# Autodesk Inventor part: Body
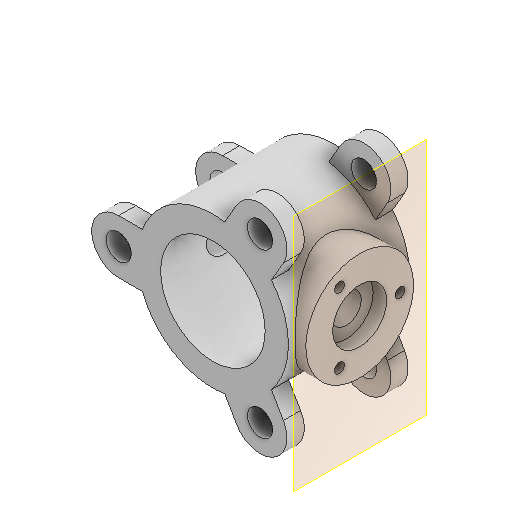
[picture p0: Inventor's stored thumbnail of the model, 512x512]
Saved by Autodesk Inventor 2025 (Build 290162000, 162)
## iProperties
Created: 2019-03
Part Number: Body
Material: Generic
Document SubType Name: Modeling
Designer: LENOVO-CADCIM
Density: 1 g/cm^3
Appearance: Default
Author: LENOVO-CADCIM
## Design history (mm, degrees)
sketch "Sketch1"
  geometry: C1 r 140 at (0, 0); C2 r 97 at (0, 0); 1 further point
  constraints: 2 centre point, 2 coincident
  dimensions: "d0" = 194 diameter of C2; "d1" = 280 diameter of C1
extrude "Extrusion1" new body sketch "Sketch1" stored distance "d2" = 225; taper "d3" = 0 deg
sketch "Sketch2"
  geometry: L1 (0, 0)-(-428, 0); L2 (-130.767, 50)-(-175, 50); L3 (-130.767, -50)-(-175, -50); C1 r 23.5 at (-175, 0); A1 r 175 centre (0, 0) between (-175, 0) and (-175, 0); A2 r 140 centre (0, 0) between (-130.767, 50) and (-130.767, -50) reference; A3 r 50 centre (-175, 0) between (-175, 50) and (-175, -50); 1 further point
  constraints: 6 end point, 6 point on circle, 3 centre point, 3 horizontal, 2 tangent, 1 coincident, 1 point on line, 1 other
  dimensions: "d4" = 350 diameter of A1; "d5" = 50 radius of A3; "d6" = 47 diameter of C1
extrude "Extrusion2" join sketch "Sketch2" distance "d7" = 32; taper "d8" = 0 deg
pattern_circular "Circular Pattern1" dims angle "d10" = 360 deg
mirror "Mirror1"
workplane "Work Plane1"
sketch "Sketch3"
  geometry: C1 r 100 at (0, 0); 1 further point
  constraints: 1 centre point, 1 coincident
  dimensions: "d13" = 200 diameter of C1
extrude "Extrusion3" join sketch "Sketch3" stored distance "d14" = 32; taper "d15" = 0 deg
sketch "Sketch4" dims "d16" = 150
  geometry: L1 (0, 0)-(102, 0); 2 further points
  constraints: 2 end point, 1 coincident, 1 horizontal, 1 horizontal alignment, 1 point on line, 2 other
hole "Hole1" sketch "Sketch4" at (75, 0) diameter "d17" = 18.376; stored, may be unused: countersink angle "d21" = 90 deg, drill point angle "d23" = 118 deg; dims "d18" = 40, "d19" = 4, "d20" = 2, "d22" = 47.3
pattern_circular "Circular Pattern2" dims angle "d25" = 360 deg
sketch "Sketch5"
  geometry: C1 r 100 at (0, 0) reference; 2 further points
  constraints: 1 coincident
hole "Hole2" sketch "Sketch5" diameter "d27" = 56; stored, may be unused: countersink angle "d31" = 90 deg, drill point angle "d33" = 118 deg; dims "d28" = 6, "d29" = 100, "d30" = 25, "d32" = 310
body "Solid1"
